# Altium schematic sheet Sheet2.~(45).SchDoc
size A3
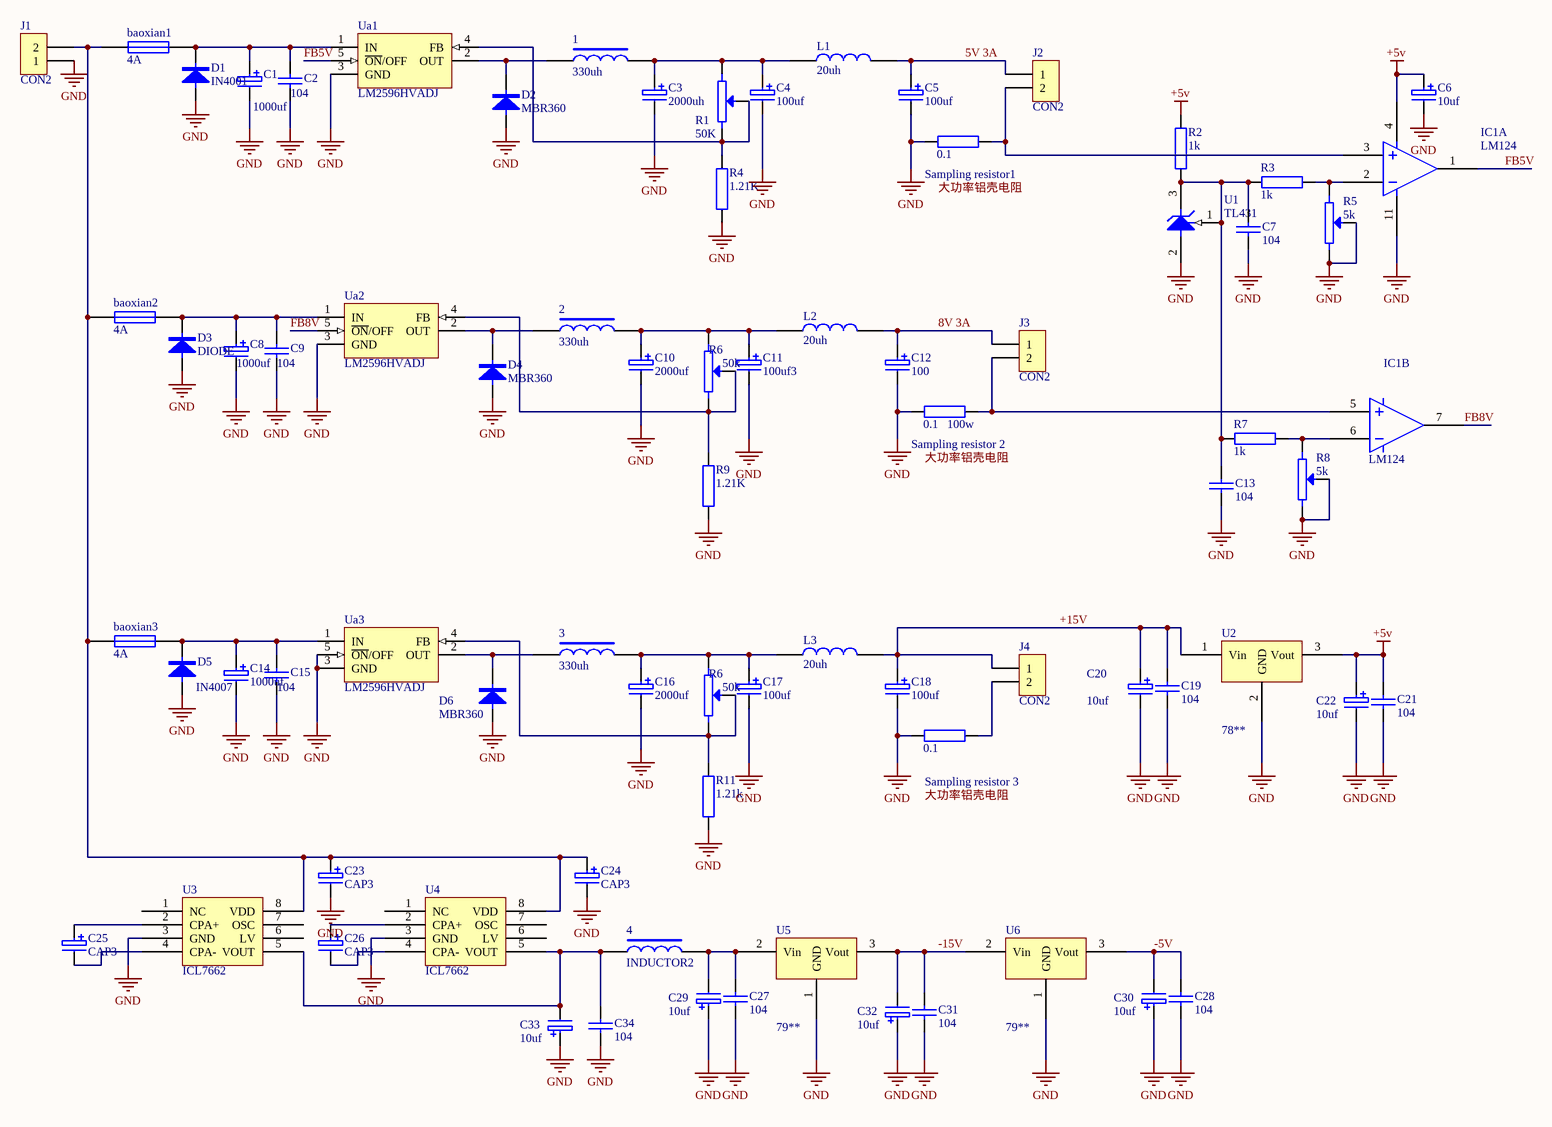
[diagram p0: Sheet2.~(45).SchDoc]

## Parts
(Parts that share a designator on the sheet are numbered #1, #2 ... from top to bottom, then left to right.)
1  330uh
2  330uh
3  330uh
4  INDUCTOR2
baoxian1  4A  [RAD0.5]
baoxian2  4A  [RAD0.5]
baoxian3  4A  [RAD0.5]
C1  1000uf  [RB2]
C2  104  [RAD0.2]
C3  2000uh  [RB3]
C4  100uf  [RB3]
C5  100uf  [RB1]
C6  10uf  [RB1]
C7  104  [RAD0.15]
C8  1000uf  [RB2]
C9  104  [RAD0.2]
C10  2000uf  [RB3]
C11  100uf3  [RB3]
C12  100  [RB1]
C13  104  [RAD0.15]
C14  1000uf  [RB2]
C15  104  [RAD0.2]
C16  2000uf  [RB3]
C17  100uf  [RB3]
C18  100uf  [RB1]
C19  104  [RAD0.15]
C20  10uf  [RB3]
C21  104  [RAD0.15]
C22  10uf  [RB3]
C23  CAP3  [RB3]
C24  CAP3  [RB3]
C25  CAP3  [RB3]
C26  CAP3  [RB3]
C27  104  [RAD0.15]
C28  104  [RAD0.15]
C29  10uf  [RB3]
C30  10uf  [RB3]
C31  104  [RAD0.15]
C32  10uf  [RB3]
C33  10uf  [RB3]
C34  104  [RAD0.15]
D1  IN4001  [DIODE0.4]
D2  MBR360  [DIODE0.2]
D3  DIODE  [DIODE0.4]
D4  MBR360  [DIODE0.2]
D5  IN4007  [DIODE0.4]
D6  MBR360  [DIODE0.2]
IC1  LM124  [DIP-14]  (parts A,B of 4)
J1  CON2  [BCON2]
J2  CON2  [BCON2]
J3  CON2  [BCON2]
J4  CON2  [BCON2]
L1  20uh  [LHF440]
L2  20uh  [LHF440]
L3  20uh  [LHF440]
R1  50K  [VR5]
R2  1k  [AXIAL0.3]
R3  1k  [AXIAL0.3]
R4  1.21K  [AXIAL0.3]
R5  5k  [VR5]
R6#1  50k  [VR5]
R6#2  50k  [VR5]
R7  1k  [AXIAL0.3]
R8  5k  [VR5]
R9  1.21K  [AXIAL0.3]
R11  1.21k  [AXIAL0.3]
Sampling_resistor1  0.1  [AXIAL0.8]
Sampling_resistor_2  0.1   100w  [AXIAL0.8]
Sampling_resistor_3  0.1  [AXIAL0.8]
U1  TL431  [TO92B]
U2  78**  [TO257V]
U3  ICL7662  [DIP-8]
U4  ICL7662  [DIP-8]
U5  79**  [TO257V]
U6  79**  [TO257V]
Ua1  LM2596HVADJ  [SIP-5]
Ua2  LM2596HVADJ  [SIP-5]
Ua3  LM2596HVADJ  [SIP-5]

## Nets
+5v: C6.1 C21.1 C22.1 IC1.4 R2.2 U2.3(Vout)
GND: C1.2 C2.2 C3.2 C4.2 C5.2 C6.2 C7.2 C8.2 C9.2 C10.2 C11.2 C12.2 C13.2 C14.2 C15.2 C16.2 C17.2 C18.2 C19.2 C20.2 C21.2 C22.2 C23.2 C24.2 C27.2 C28.2 C29.1 C30.1 C31.2 C32.1 C33.1 C34.2 D1.1 D2.1 D3.1 D4.1 D5.1 D6.1 IC1.11 J1.1 R4.1 R5.2(VT) R5.3 R8.2(VT) R8.3 R9.1 R11.1 Sampling_resistor1.2 Sampling_resistor_2.2 Sampling_resistor_3.2 U1.2(A) U2.2(GND) U3.3(GND) U4.3(GND) U5.1(GND) U6.1(GND) Ua1.3(GND) Ua2.3(GND) Ua3.3(GND) Ua3.5(~{ON}/OFF)
5V 3A: C5.1 J2.1 L1.2
8V 3A: C12.1 J3.1 L2.2
+15V: C18.1 C19.1 C20.1 J4.1 L3.2 U2.1(Vin)
-5V: C28.1 C30.2 U6.3(Vout)
-15V: C31.1 C32.2 U5.3(Vout) U6.2(Vin)
FB5V: IC1.1 Ua1.5(~{ON}/OFF)
FB8V: IC1.7 Ua2.5(~{ON}/OFF)
Net1_1: 1.1 D2.2 Ua1.2(OUT)
Net1_2: 1.2 C3.1 C4.1 L1.1 R1.1
Net2_1: 2.1 D4.2 Ua2.2(OUT)
Net2_2: 2.2 C10.1 C11.1 L2.1 R6#1.1
Net3_1: 3.1 D6.2 Ua3.2(OUT)
Net3_2: 3.2 C16.1 C17.1 L3.1 R6#2.1
Net4_1: 4.1 C33.2 C34.1 U3.5(VOUT) U4.5(VOUT)
Net4_2: 4.2 C27.1 C29.2 U5.2(Vin)
Netbaoxian1_1: baoxian1.1 C1.1 C2.1 D1.2 Ua1.1(IN)
Netbaoxian1_2: baoxian1.2 baoxian2.2 baoxian3.2 C23.1 C24.1 J1.2 U3.8(VDD) U4.8(VDD)
Netbaoxian2_1: baoxian2.1 C8.1 C9.1 D3.2 Ua2.1(IN)
Netbaoxian3_1: baoxian3.1 C14.1 C15.1 D5.2 Ua3.1(IN)
NetC7_1: C7.1 C13.1 R2.1 R3.1 R7.1 U1.1(REF) U1.3(K)
NetC25_1: C25.1 U3.2(CPA+)
NetC25_2: C25.2 U3.4(CPA-)
NetC26_1: C26.1 U4.2(CPA+)
NetC26_2: C26.2 U4.4(CPA-)
NetIC1_2: IC1.2 R3.2 R5.1
NetIC1_3: IC1.3 J2.2 Sampling_resistor1.1
NetIC1_5: IC1.5 J3.2 Sampling_resistor_2.1
NetIC1_6: IC1.6 R7.2 R8.1
NetJ4_2: J4.2 Sampling_resistor_3.1
NetR1_2: R1.2(VT) R1.3 R4.2 Ua1.4(FB)
NetR6#1_2: R6#1.2(VT) R6#1.3 R9.2 Ua2.4(FB)
NetR6#2_2: R6#2.2(VT) R6#2.3 R11.2 Ua3.4(FB)

Not connected (* = marked no-connect by the designer): U3 1(NC) 6(LV) 7(OSC); U4 1(NC) 6(LV) 7(OSC)

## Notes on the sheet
- Labels drawn without touching a wire or pin: 大功率铝壳电阻

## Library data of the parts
1-3 = INDUCTOR2
baoxian1-baoxian3 = FUSE1: Fuse
C1 C3-C6 C8 C10-C12 C14 C16-C18 C20 C22 C29 C30 C32 C33 = CAP3
C2 C7 C9 C13 C15 C19 C21 C27 C28 C31 C34 = CAP1
D1 D2 D4-D6 = DIODE
J1-J4 = CON2: Connector
L1-L3 = INDUCTOR
R1 R5 R6#1 R6#2 R8 = RPOT2: Potentiometer
R2-R4 R7 R9 R11 Sampling_resistor1 Sampling_resistor_2 Sampling_resistor_3 = RES
U1 = TL431: Programmable Voltage Reference
Ua1-Ua3 = LM2596T-5.0: Simple Switcher Power Converter 150 kHz 3A Step Down Voltage Regulator; PackageDocument: 2000; Note: Tab is connected to GND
